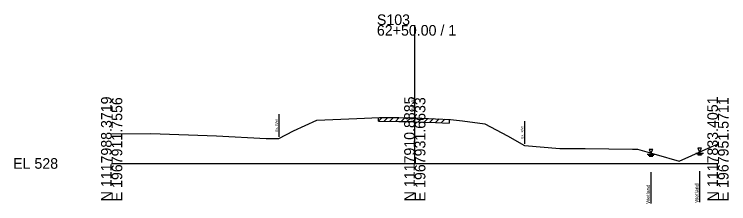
# Model space of a CAD drawing. Extents: x -26 to 163, y -10 to 24018.
# Drawn here: x -25.7 to 162.8, y 10489.4 to 10539.4 of the extents above; entities that cross this region are included whole.
import ezdxf

# ---------------------------------------------------------------- set-up
doc = ezdxf.new("R2010")
doc.units = 0
for name, color, linetype in [('RD_GPK_XS_Cell', 7, 'Continuous'), ('RD_XS_ExGround', 7, 'Continuous'), ('RD_XS_ExPaveRet', 7, 'Continuous'), ('RD_XS_ExRW', 7, 'Continuous'), ('RD_XS_EXWetland', 7, 'Continuous'), ('RD_XS_TX_Elev_EX', 7, 'Continuous')]:
    doc.layers.add(name, color=color, linetype=linetype)

msp = doc.modelspace()

# ---------------------------------------------------------------- linework, layer by layer
at = {"layer": 'RD_GPK_XS_Cell'}
for p, q in [((80, 10500), (80, 10536.55)), ((0, 10500), (80, 10500)), ((80, 10500), (160, 10500))]:
    msp.add_line(p, q, dxfattribs=at)
at = {"layer": 'RD_XS_ExGround'}
msp.add_lwpolyline([(0, 10507.79), (10.35, 10507.91), (27.7, 10507.26), (40.79, 10506.57), (44.11, 10506.55), (47.95, 10508.58), (54.12, 10511.43), (64.71, 10511.91), (70.71, 10512.18), (75.83, 10512.1), (79.06, 10512.04), (80, 10512.01), (85.44, 10511.81), (89.39, 10511.64), (92.63, 10511.25), (98.51, 10510.43), (104.47, 10507.3), (108.91, 10504.71), (118.26, 10503.99), (124.93, 10503.94), (137.45, 10503.8), (138.75, 10503.76), (143.66, 10502.34), (149.73, 10500.58), (158.98, 10504.73), (160, 10505.09)], dxfattribs=at)
at = {"layer": 'RD_XS_ExPaveRet'}
for p, q in [((70.43, 10511.17), (71.43, 10512.17)), ((70.43, 10511.17), (70.43, 10512.17)), ((70.43, 10511.17), (70.71, 10511.18)), ((70.71, 10511.18), (75.83, 10511.1)), ((71.93, 10511.16), (72.91, 10512.15)), ((73.43, 10511.14), (74.41, 10512.12)), ((74.93, 10511.11), (75.91, 10512.1)), ((75.83, 10511.1), (79.06, 10511.04)), ((76.43, 10511.09), (77.41, 10512.07)), ((77.93, 10511.06), (78.91, 10512.04)), ((79.06, 10511.04), (80, 10511.01)), ((79.43, 10511.03), (80.4, 10511.99)), ((80, 10511.01), (85.44, 10510.81)), ((80.93, 10510.97), (81.9, 10511.94)), ((82.43, 10510.92), (83.4, 10511.89)), ((83.93, 10510.87), (84.9, 10511.83)), ((85.43, 10510.81), (86.39, 10511.77)), ((85.44, 10510.81), (89.08, 10510.66)), ((86.93, 10510.75), (87.89, 10511.71)), ((89.08, 10511.66), (89.08, 10510.66))]:
    msp.add_line(p, q, dxfattribs=at)
at = {"layer": 'RD_XS_ExRW'}
for p, q in [((44.11, 10513.05), (44.11, 10507.05)), ((108.91, 10511.21), (108.91, 10505.21))]:
    msp.add_line(p, q, dxfattribs=at)
at = {"layer": 'RD_XS_EXWetland'}
for p, q in [((141.82, 10503.72), (142.32, 10502.72)), ((142.82, 10503.72), (141.82, 10503.72)), ((142.32, 10502.72), (142.82, 10503.72)), ((154.65, 10504.01), (155.15, 10503.01)), ((155.65, 10504.01), (154.65, 10504.01)), ((155.15, 10503.01), (155.65, 10504.01)), ((141.32, 10502.47), (143.32, 10502.47)), ((141.57, 10502.22), (143.07, 10502.22)), ((141.82, 10501.97), (142.82, 10501.97)), ((154.15, 10502.76), (156.15, 10502.76)), ((154.4, 10502.51), (155.9, 10502.51)), ((154.65, 10502.26), (155.65, 10502.26)), ((142.32, 10497.72), (142.32, 10489.47)), ((155.15, 10498.01), (155.15, 10489.76))]:
    msp.add_line(p, q, dxfattribs=at)

# ---------------------------------------------------------------- texts
at = {"layer": 'RD_GPK_XS_Cell'}
for s, p in [('S103', (70, 10536.55)), ('62+50.00 / 1', (70, 10533.75)), ('EL 528', (-26, 10498.6))]:
    msp.add_text(s, height=2.8, dxfattribs=at).set_placement(p)
for s, p in [('N 1117988.3719', (0, 10490)), ('E 1967911.7556', (2.8, 10490)), ('N 1117910.8885', (80, 10490)), ('E 1967931.6633', (82.8, 10490)), ('N 1117833.4051', (160, 10490)), ('E 1967951.5711', (162.8, 10490))]:
    msp.add_text(s, height=2.8, rotation=90, dxfattribs=at).set_placement(p)
at = {"layer": 'RD_XS_ExRW'}
for p in [(43.86, 10508.39), (108.66, 10506.56)]:
    msp.add_text('Ex. R/W ', height=0.65, rotation=90, dxfattribs=at).set_placement(p)
at = {"layer": 'RD_XS_EXWetland'}
for p in [(142.07, 10489.37), (154.9, 10489.65)]:
    msp.add_text('Wetland ', height=1, rotation=90, dxfattribs=at).set_placement(p)
at = {"layer": 'RD_XS_TX_Elev_EX'}
msp.add_text('540.01', height=0.8, rotation=90, dxfattribs=at).set_placement((79.9, 10514.01))

doc.saveas('drawing.dxf')
